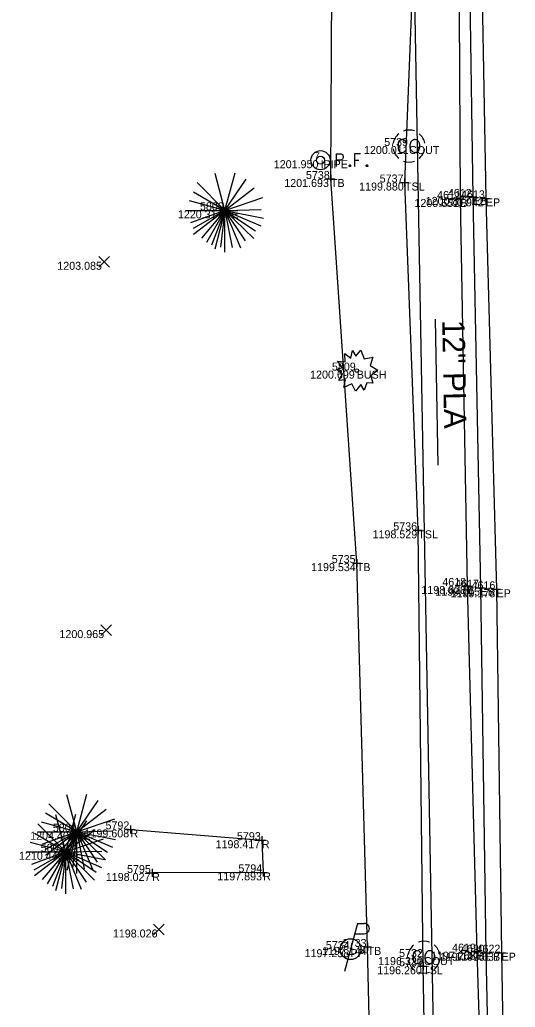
# Model space of a CAD drawing. Extents: x 2044996 to 2050343, y 455232 to 458054.
# Drawn here: x 2047573.6 to 2047635.5, y 456392.6 to 456516 of the extents above; entities that cross this region are included whole.
import ezdxf

# ---------------------------------------------------------------- set-up
doc = ezdxf.new("R2010")
doc.units = 0
for name, color, linetype in [('DR_X_Cells', 7, 'Continuous'), ('DR_X_Erosion_Control', 7, 'Continuous'), ('DR_X_Storm_Sewer', 7, 'Continuous'), ('DR_X_Text', 7, 'Continuous'), ('DT_X_Contour_Minor', 7, 'Continuous'), ('DT_X_Contour_Text', 7, 'Continuous'), ('DT_X_Spot_Elev', 7, 'Continuous'), ('DT_X_Triangles', 7, 'Continuous'), ('DT_X_Void', 7, 'Continuous'), ('PV_X_EOP', 7, 'Continuous'), ('PV_X_Shoulder_Aggregate', 7, 'Continuous'), ('SV_X_Break_Lines', 7, 'Continuous'), ('SV_X_Toe_of_Slope', 7, 'Continuous'), ('SV_X_Top_of_Bank', 7, 'Continuous'), ('UT_X_Electric_Cells', 7, 'Continuous'), ('VG_X_Cells', 7, 'Continuous'), ('XS_X_Ground_Line', 7, 'Continuous')]:
    doc.layers.add(name, color=color, linetype=linetype)

msp = doc.modelspace()

# ---------------------------------------------------------------- linework, layer by layer
at = {"layer": 'DR_X_Cells'}
for p, q in [((2047622.18, 456500.21), (2047622.18, 456500.21)), ((2047624.05, 456398.84), (2047624.05, 456398.84))]:
    msp.add_line(p, q, dxfattribs=at)
for points in [[(2047621.76, 456500.7), (2047621.7, 456500.84), (2047621.64, 456500.91), (2047621.58, 456500.96), (2047621.52, 456500.99), (2047621.39, 456501.01), (2047621.25, 456501.01), (2047621.07, 456500.96), (2047620.97, 456500.89), (2047620.92, 456500.82), (2047620.87, 456500.74), (2047620.83, 456500.6), (2047620.82, 456500.34), (2047620.82, 456500.16), (2047620.82, 456500.03), (2047620.83, 456499.92), (2047620.87, 456499.71), (2047620.88, 456499.68), (2047620.93, 456499.59), (2047620.98, 456499.53), (2047621.07, 456499.46), (2047621.15, 456499.44), (2047621.25, 456499.41), (2047621.36, 456499.41), (2047621.47, 456499.43), (2047621.51, 456499.44), (2047621.56, 456499.46), (2047621.61, 456499.51), (2047621.68, 456499.58), (2047621.73, 456499.65), (2047621.76, 456499.71)], [(2047622.78, 456501), (2047622.75, 456500.99), (2047622.71, 456500.97), (2047622.65, 456500.94), (2047622.61, 456500.91), (2047622.55, 456500.86), (2047622.49, 456500.81), (2047622.47, 456500.79), (2047622.43, 456500.74), (2047622.37, 456500.61), (2047622.32, 456500.48), (2047622.29, 456500.37), (2047622.28, 456500.21), (2047622.29, 456500.03), (2047622.33, 456499.9), (2047622.37, 456499.8), (2047622.39, 456499.75), (2047622.43, 456499.69), (2047622.48, 456499.63), (2047622.52, 456499.59), (2047622.56, 456499.55), (2047622.61, 456499.51), (2047622.67, 456499.48), (2047622.78, 456499.43), (2047622.85, 456499.41), (2047622.97, 456499.41), (2047623.02, 456499.43), (2047623.07, 456499.44), (2047623.14, 456499.46), (2047623.2, 456499.5), (2047623.24, 456499.53), (2047623.28, 456499.55), (2047623.31, 456499.59), (2047623.35, 456499.64), (2047623.38, 456499.68), (2047623.4, 456499.71), (2047623.43, 456499.75), (2047623.46, 456499.83), (2047623.5, 456499.92), (2047623.53, 456500.02), (2047623.54, 456500.11), (2047623.54, 456500.12), (2047623.54, 456500.21), (2047623.54, 456500.28), (2047623.53, 456500.38), (2047623.5, 456500.48), (2047623.48, 456500.56), (2047623.44, 456500.65), (2047623.4, 456500.72), (2047623.34, 456500.8), (2047623.29, 456500.85), (2047623.24, 456500.9), (2047623.19, 456500.94), (2047623.11, 456500.97), (2047623.04, 456501), (2047622.96, 456501.01), (2047622.87, 456501.01), (2047622.78, 456501)], [(2047623.64, 456399.32), (2047623.58, 456399.46), (2047623.51, 456399.54), (2047623.45, 456399.59), (2047623.4, 456399.61), (2047623.26, 456399.64), (2047623.12, 456399.64), (2047622.95, 456399.59), (2047622.85, 456399.51), (2047622.8, 456399.45), (2047622.75, 456399.36), (2047622.71, 456399.22), (2047622.7, 456398.97), (2047622.7, 456398.78), (2047622.7, 456398.65), (2047622.71, 456398.54), (2047622.75, 456398.34), (2047622.76, 456398.3), (2047622.81, 456398.21), (2047622.86, 456398.15), (2047622.95, 456398.09), (2047623.02, 456398.06), (2047623.12, 456398.04), (2047623.24, 456398.04), (2047623.35, 456398.05), (2047623.39, 456398.06), (2047623.44, 456398.09), (2047623.49, 456398.14), (2047623.55, 456398.2), (2047623.6, 456398.28), (2047623.64, 456398.34)], [(2047624.66, 456399.62), (2047624.62, 456399.61), (2047624.59, 456399.6), (2047624.52, 456399.56), (2047624.48, 456399.54), (2047624.42, 456399.49), (2047624.37, 456399.43), (2047624.35, 456399.41), (2047624.31, 456399.36), (2047624.25, 456399.23), (2047624.19, 456399.11), (2047624.17, 456398.99), (2047624.16, 456398.83), (2047624.17, 456398.65), (2047624.21, 456398.53), (2047624.25, 456398.43), (2047624.27, 456398.38), (2047624.31, 456398.31), (2047624.36, 456398.25), (2047624.4, 456398.21), (2047624.43, 456398.17), (2047624.48, 456398.14), (2047624.55, 456398.1), (2047624.66, 456398.05), (2047624.72, 456398.04), (2047624.85, 456398.04), (2047624.9, 456398.05), (2047624.95, 456398.06), (2047625.01, 456398.09), (2047625.08, 456398.12), (2047625.11, 456398.15), (2047625.15, 456398.17), (2047625.19, 456398.21), (2047625.23, 456398.26), (2047625.25, 456398.3), (2047625.28, 456398.34), (2047625.3, 456398.38), (2047625.34, 456398.45), (2047625.38, 456398.54), (2047625.4, 456398.64), (2047625.42, 456398.73), (2047625.42, 456398.74), (2047625.42, 456398.83), (2047625.42, 456398.91), (2047625.4, 456399.01), (2047625.38, 456399.11), (2047625.35, 456399.18), (2047625.32, 456399.27), (2047625.28, 456399.35), (2047625.21, 456399.42), (2047625.16, 456399.47), (2047625.11, 456399.52), (2047625.06, 456399.56), (2047624.99, 456399.6), (2047624.91, 456399.62), (2047624.84, 456399.64), (2047624.75, 456399.64), (2047624.66, 456399.62)]]:
    msp.add_lwpolyline(points, dxfattribs=at)
for centre, start, end in [((2047622.18, 456500.21), 70.0577, 110.1061), ((2047622.18, 456500.21), 130.0806, 170.0721), ((2047622.18, 456500.21), 10.0169, 50.0392), ((2047622.18, 456500.21), 190.0169, 230.0392), ((2047622.18, 456500.21), 310.0114, 350.0264), ((2047622.18, 456500.21), 250.0577, 290.0473), ((2047624.05, 456398.83), 70.0577, 110.1061), ((2047624.05, 456398.83), 130.0806, 170.0721), ((2047624.05, 456398.83), 10.0169, 50.0392), ((2047624.05, 456398.83), 190.0169, 230.0392), ((2047624.05, 456398.83), 310.0114, 350.0264), ((2047624.05, 456398.83), 250.0577, 290.0473)]:
    msp.add_arc(centre, 2, start, end, dxfattribs=at)
at = {"layer": 'DR_X_Erosion_Control'}
msp.add_lwpolyline([(2047587.38, 456414.8), (2047603.8, 456413.45), (2047603.96, 456409.43), (2047590.09, 456409.35)], dxfattribs=at)
at = {"layer": 'DR_X_Storm_Sewer'}
msp.add_line((2047618.84, 456740.61), (2047628.62, 456202.21), dxfattribs=at)
at = {"layer": 'DR_X_Text'}
msp.add_line((2047625.83, 456460.34), (2047625.5, 456478.56), dxfattribs=at)
at = {"layer": 'DT_X_Spot_Elev'}
for p, q in [((2047583.43, 456485.07), (2047584.77, 456486.41)), ((2047583.43, 456486.41), (2047584.77, 456485.07)), ((2047583.7, 456439.04), (2047585.04, 456440.38)), ((2047583.7, 456440.38), (2047585.04, 456439.04)), ((2047590.26, 456401.63), (2047591.59, 456402.96)), ((2047590.26, 456402.96), (2047591.59, 456401.63))]:
    msp.add_line(p, q, dxfattribs=at)
at = {"layer": 'DT_X_Void'}
for p, q in [((2047611.93, 456496.09), (2047612.93, 456496.09)), ((2047612.43, 456496.59), (2047612.43, 456495.59)), ((2047612.43, 456496.09), (2047612.43, 456496.09)), ((2047621.68, 456496.15), (2047621.68, 456495.15)), ((2047621.18, 456495.65), (2047622.18, 456495.65)), ((2047621.68, 456495.65), (2047621.68, 456495.65)), ((2047628.08, 456493.59), (2047629.08, 456493.59)), ((2047628.58, 456494.09), (2047628.58, 456493.09)), ((2047628.58, 456493.59), (2047628.58, 456493.59)), ((2047629.65, 456493.85), (2047630.65, 456493.85)), ((2047630.15, 456494.35), (2047630.15, 456493.35)), ((2047630.15, 456493.85), (2047630.15, 456493.85)), ((2047631.28, 456493.67), (2047632.28, 456493.67)), ((2047631.78, 456494.17), (2047631.78, 456493.17)), ((2047631.78, 456493.67), (2047631.78, 456493.67)), ((2047623.34, 456452.68), (2047623.34, 456451.68)), ((2047622.84, 456452.18), (2047623.84, 456452.18)), ((2047623.34, 456452.18), (2047623.34, 456452.18)), ((2047615.16, 456448.08), (2047616.16, 456448.08)), ((2047615.66, 456448.58), (2047615.66, 456447.58)), ((2047615.66, 456448.08), (2047615.66, 456448.08)), ((2047628.96, 456445.22), (2047629.96, 456445.22)), ((2047629.46, 456445.72), (2047629.46, 456444.72)), ((2047629.46, 456445.22), (2047629.46, 456445.22)), ((2047631.11, 456445.51), (2047631.11, 456444.51)), ((2047633.11, 456445.31), (2047633.11, 456444.31)), ((2047630.61, 456445.01), (2047631.61, 456445.01)), ((2047631.11, 456445.01), (2047631.11, 456445.01)), ((2047632.61, 456444.81), (2047633.61, 456444.81)), ((2047633.11, 456444.81), (2047633.11, 456444.81)), ((2047586.88, 456414.8), (2047587.88, 456414.8)), ((2047587.38, 456415.3), (2047587.38, 456414.3)), ((2047587.38, 456414.8), (2047587.38, 456414.8)), ((2047603.3, 456413.45), (2047604.3, 456413.45)), ((2047603.8, 456413.95), (2047603.8, 456412.95)), ((2047603.8, 456413.45), (2047603.8, 456413.45)), ((2047589.59, 456409.35), (2047590.59, 456409.35)), ((2047590.09, 456409.85), (2047590.09, 456408.85)), ((2047590.09, 456409.35), (2047590.09, 456409.35)), ((2047603.46, 456409.43), (2047604.46, 456409.43)), ((2047603.96, 456409.93), (2047603.96, 456408.93)), ((2047603.96, 456409.43), (2047603.96, 456409.43)), ((2047616.51, 456400.11), (2047617.51, 456400.11)), ((2047617.01, 456400.61), (2047617.01, 456399.61)), ((2047617.01, 456400.11), (2047617.01, 456400.11)), ((2047630.16, 456399.52), (2047631.16, 456399.52)), ((2047630.66, 456400.02), (2047630.66, 456399.02)), ((2047630.66, 456399.52), (2047630.66, 456399.52)), ((2047631.78, 456399.88), (2047631.78, 456398.88)), ((2047633.74, 456399.89), (2047633.74, 456398.89)), ((2047623.95, 456398.19), (2047623.95, 456397.19)), ((2047631.28, 456399.38), (2047632.28, 456399.38)), ((2047631.78, 456399.38), (2047631.78, 456399.38)), ((2047633.24, 456399.39), (2047634.24, 456399.39)), ((2047633.74, 456399.39), (2047633.74, 456399.39)), ((2047623.45, 456397.69), (2047624.45, 456397.69)), ((2047623.95, 456397.69), (2047623.95, 456397.69))]:
    msp.add_line(p, q, dxfattribs=at)
at = {"layer": 'PV_X_EOP'}
for p, q in [((2047630.94, 456539.92), (2047631.78, 456493.67)), ((2047631.78, 456493.67), (2047633.11, 456444.81)), ((2047633.11, 456444.81), (2047633.74, 456399.39)), ((2047633.74, 456399.39), (2047634.49, 456356.94))]:
    msp.add_line(p, q, dxfattribs=at)
at = {"layer": 'PV_X_Shoulder_Aggregate'}
for p, q in [((2047629.49, 456539.93), (2047630.15, 456493.85)), ((2047630.15, 456493.85), (2047631.11, 456445.01)), ((2047631.11, 456445.01), (2047631.78, 456399.38)), ((2047631.78, 456399.38), (2047632.62, 456356.87))]:
    msp.add_line(p, q, dxfattribs=at)
at = {"layer": 'SV_X_Break_Lines'}
msp.add_lwpolyline([(2047625.21, 456638.95), (2047627.11, 456588.81), (2047628.32, 456540.51), (2047628.58, 456493.59), (2047629.46, 456445.22), (2047630.66, 456399.52), (2047631.97, 456357.07), (2047632.12, 456312.85), (2047632.56, 456284.1)], dxfattribs=at)
at = {"layer": 'SV_X_Toe_of_Slope'}
msp.add_lwpolyline([(2047627.42, 456261.1), (2047625.53, 456304.38), (2047624.71, 456355.98), (2047623.95, 456397.69), (2047623.34, 456452.18), (2047621.68, 456495.65), (2047623.55, 456542.59), (2047620.93, 456580.31), (2047618.38, 456635.97)], dxfattribs=at)
at = {"layer": 'SV_X_Top_of_Bank'}
msp.add_lwpolyline([(2047619.16, 456260.18), (2047618.27, 456307.13), (2047618.14, 456352.85), (2047617.01, 456400.11), (2047615.66, 456448.08), (2047612.43, 456496.09), (2047612.66, 456543.64), (2047611.43, 456577.89), (2047611.46, 456637.59)], dxfattribs=at)
at = {"layer": 'UT_X_Electric_Cells'}
for p, q in [((2047615.73, 456403.03), (2047614.13, 456397.03)), ((2047615.73, 456403.03), (2047616.58, 456403.03)), ((2047615.39, 456401.76), (2047616.58, 456401.76))]:
    msp.add_line(p, q, dxfattribs=at)
msp.add_circle((2047614.88, 456399.83), 1.3, dxfattribs=at)
msp.add_arc((2047616.6, 456402.4), 0.638, 268.8767, 91.1233, dxfattribs=at)
at = {"layer": 'VG_X_Cells'}
for p, q in [((2047599.19, 456492.17), (2047597.96, 456496.78)), ((2047599.19, 456492.17), (2047600.45, 456496.87)), ((2047599.19, 456492.17), (2047601.85, 456496.05)), ((2047599.19, 456492.17), (2047595.28, 456494.46)), ((2047599.19, 456492.17), (2047595.7, 456495.65)), ((2047599.19, 456492.17), (2047602.85, 456494.97)), ((2047599.19, 456492.17), (2047594.78, 456493.35)), ((2047599.19, 456492.17), (2047603.93, 456493.77)), ((2047594.26, 456492.17), (2047599.19, 456492.17)), ((2047599.19, 456492.17), (2047594.9, 456490.61)), ((2047599.19, 456492.17), (2047595.21, 456489.89)), ((2047599.19, 456492.17), (2047595.28, 456489.17)), ((2047599.19, 456492.17), (2047596.25, 456488.7)), ((2047599.19, 456492.17), (2047596.87, 456488.15)), ((2047599.19, 456492.17), (2047597.53, 456487.83)), ((2047599.19, 456492.17), (2047597.93, 456487.31)), ((2047599.19, 456492.17), (2047598.65, 456487.58)), ((2047599.19, 456492.17), (2047603.7, 456492.26)), ((2047599.19, 456486.93), (2047599.19, 456492.17)), ((2047599.19, 456492.17), (2047600.11, 456487.53)), ((2047599.19, 456492.17), (2047601.12, 456487.5)), ((2047599.19, 456492.17), (2047601.73, 456488.37)), ((2047599.19, 456492.17), (2047602.78, 456488.65)), ((2047599.19, 456492.17), (2047603.01, 456489.61)), ((2047599.19, 456492.17), (2047603.66, 456490.23)), ((2047599.19, 456492.17), (2047604.02, 456491.21)), ((2047580.69, 456414.51), (2047581.95, 456419.21)), ((2047580.69, 456414.51), (2047577.2, 456418)), ((2047580.69, 456414.51), (2047579.46, 456419.13)), ((2047580.69, 456414.51), (2047583.35, 456418.4)), ((2047580.69, 456414.51), (2047576.79, 456416.81)), ((2047579.3, 456412), (2047580.56, 456416.69)), ((2047580.69, 456414.51), (2047584.35, 456417.32)), ((2047579.3, 456412), (2047575.81, 456415.48)), ((2047580.69, 456414.51), (2047576.28, 456415.7)), ((2047579.3, 456412), (2047578.06, 456416.61)), ((2047579.3, 456412), (2047581.95, 456415.88)), ((2047580.69, 456414.51), (2047585.43, 456416.12)), ((2047579.3, 456412), (2047575.39, 456414.29)), ((2047575.76, 456414.51), (2047580.69, 456414.51)), ((2047580.69, 456414.51), (2047576.4, 456412.95)), ((2047580.69, 456414.51), (2047576.71, 456412.23)), ((2047580.69, 456414.51), (2047576.79, 456411.52)), ((2047580.69, 456414.51), (2047577.75, 456411.05)), ((2047580.69, 456414.51), (2047578.37, 456410.5)), ((2047580.69, 456414.51), (2047579.03, 456410.17)), ((2047579.3, 456412), (2047582.96, 456414.8)), ((2047580.69, 456414.51), (2047579.43, 456409.66)), ((2047580.69, 456414.51), (2047580.15, 456409.92)), ((2047580.69, 456414.51), (2047585.2, 456414.6)), ((2047580.69, 456409.27), (2047580.69, 456414.51)), ((2047580.69, 456414.51), (2047581.61, 456409.88)), ((2047580.69, 456414.51), (2047582.63, 456409.84)), ((2047580.69, 456414.51), (2047583.23, 456410.72)), ((2047580.69, 456414.51), (2047584.28, 456410.99)), ((2047580.69, 456414.51), (2047584.51, 456411.96)), ((2047580.69, 456414.51), (2047585.16, 456412.57)), ((2047580.69, 456414.51), (2047585.52, 456413.55)), ((2047579.3, 456412), (2047574.89, 456413.18)), ((2047579.3, 456412), (2047584.04, 456413.6)), ((2047574.36, 456412), (2047579.3, 456412)), ((2047579.3, 456412), (2047575.01, 456410.43)), ((2047579.3, 456412), (2047575.32, 456409.71)), ((2047579.3, 456412), (2047575.39, 456409)), ((2047579.3, 456412), (2047576.35, 456408.53)), ((2047579.3, 456412), (2047576.98, 456407.98)), ((2047579.3, 456412), (2047577.63, 456407.66)), ((2047579.3, 456412), (2047578.04, 456407.14)), ((2047579.3, 456412), (2047578.76, 456407.4)), ((2047579.3, 456412), (2047583.81, 456412.09)), ((2047579.3, 456406.76), (2047579.3, 456412)), ((2047579.3, 456412), (2047580.22, 456407.36)), ((2047579.3, 456412), (2047581.23, 456407.33)), ((2047579.3, 456412), (2047581.84, 456408.2)), ((2047579.3, 456412), (2047582.89, 456408.47)), ((2047579.3, 456412), (2047583.12, 456409.44)), ((2047579.3, 456412), (2047583.76, 456410.05)), ((2047579.3, 456412), (2047584.13, 456411.04))]:
    msp.add_line(p, q, dxfattribs=at)
msp.add_lwpolyline([(2047615.56, 456473.95), (2047616.17, 456474.69), (2047616.58, 456473.63), (2047617.67, 456473.81), (2047617.34, 456472.8), (2047618.28, 456472.21), (2047617.42, 456471.47), (2047617.67, 456470.56), (2047616.92, 456470.63), (2047616.6, 456469.71), (2047616.17, 456470.4), (2047615.49, 456469.59), (2047615.06, 456470.47), (2047614.04, 456470.04), (2047614.23, 456470.99), (2047613.42, 456470.9), (2047613.89, 456471.69), (2047613.13, 456472.26), (2047613.86, 456472.52), (2047613.26, 456473.33), (2047614.19, 456473.22), (2047614.16, 456474.26), (2047614.91, 456473.69), (2047615.12, 456474.67), (2047615.56, 456473.95)], dxfattribs=at)
msp.add_circle((2047615.65, 456472.14), 0.23, dxfattribs=at)
at = {"layer": 'XS_X_Ground_Line'}
for points in [[(2047613.12, 456497.64), (2047613.12, 456499.24), (2047613.65, 456499.24), (2047613.71, 456499.23), (2047613.79, 456499.2), (2047613.82, 456499.18), (2047613.85, 456499.15), (2047613.9, 456499.09), (2047613.93, 456499.02), (2047613.95, 456498.92), (2047613.95, 456498.77), (2047613.94, 456498.72), (2047613.92, 456498.65), (2047613.87, 456498.56), (2047613.83, 456498.52), (2047613.8, 456498.5), (2047613.74, 456498.47), (2047613.65, 456498.46), (2047613.12, 456498.46)], [(2047616.13, 456499.24), (2047615.37, 456499.24), (2047615.37, 456497.64)], [(2047615.37, 456498.46), (2047615.91, 456498.46)], [(2047614.77, 456497.85), (2047614.82, 456497.85), (2047614.86, 456497.83), (2047614.89, 456497.78), (2047614.89, 456497.71), (2047614.86, 456497.66), (2047614.82, 456497.64), (2047614.77, 456497.64), (2047614.73, 456497.66), (2047614.7, 456497.71), (2047614.7, 456497.78), (2047614.73, 456497.83), (2047614.77, 456497.85)], [(2047616.92, 456497.85), (2047616.97, 456497.85), (2047617, 456497.83), (2047617.04, 456497.78), (2047617.04, 456497.71), (2047617, 456497.66), (2047616.97, 456497.64), (2047616.92, 456497.64), (2047616.88, 456497.66), (2047616.85, 456497.71), (2047616.85, 456497.78), (2047616.88, 456497.83), (2047616.92, 456497.85)]]:
    msp.add_lwpolyline(points, dxfattribs=at)
for radius in [1.2, 0.495]:
    msp.add_circle((2047611.13, 456498.44), radius, dxfattribs=at)

# ---------------------------------------------------------------- texts
at = {"layer": 'DR_X_Text'}
msp.add_text('12" PLA', height=2.8, rotation=271.0413, dxfattribs=at).set_placement((2047626.33, 456478.47))
at = {"layer": 'DT_X_Contour_Minor'}
for s, p in [('1200.011', (2047616.56, 456499.21)), ('1201.950', (2047605.29, 456497.44)), ('1201.693', (2047606.6, 456495.09)), ('1199.880', (2047615.95, 456494.65)), ('1200.651', (2047622.86, 456492.59)), ('1200.877', (2047624.27, 456492.85)), ('1200.942', (2047625.95, 456492.67)), ('1220.317', (2047593.31, 456491.17)), ('1203.085', (2047578.25, 456484.74)), ('1200.699', (2047609.83, 456471.14)), ('1198.529', (2047617.63, 456451.18)), ('1199.534', (2047609.95, 456447.08)), ('1198.828', (2047623.72, 456444.22)), ('1199.115', (2047625.47, 456444.01)), ('1199.178', (2047627.38, 456443.81)), ('1200.965', (2047578.52, 456438.71)), ('1204.402', (2047574.86, 456413.51)), ('1199.608', (2047581.65, 456413.8)), ('1198.417', (2047598.02, 456412.45)), ('1210.446', (2047573.46, 456411)), ('1198.027', (2047584.31, 456408.35)), ('1197.893', (2047598.24, 456408.43)), ('1198.026', (2047585.19, 456401.29)), ('1197.258', (2047609.14, 456398.83)), ('1197.144', (2047611.31, 456399.11)), ('1197.268', (2047624.93, 456398.52)), ('1197.637', (2047627.96, 456398.39)), ('1196.320', (2047618.32, 456397.84)), ('1197.496', (2047626.05, 456398.38)), ('1196.260', (2047618.21, 456396.69))]:
    msp.add_text(s, height=1, dxfattribs=at).set_placement(p)
at = {"layer": 'DT_X_Contour_Text'}
for s, p in [('COUT', (2047622.18, 456499.21)), ('IPIPE', (2047611.13, 456497.44)), ('TB', (2047612.43, 456495.09)), ('TSL', (2047621.68, 456494.65)), ('B', (2047628.58, 456492.59)), ('EB', (2047630.15, 456492.85)), ('EP', (2047631.78, 456492.67)), ('TE', (2047599.19, 456491.17)), ('BUSH', (2047615.65, 456471.14)), ('TSL', (2047623.34, 456451.18)), ('TB', (2047615.66, 456447.08)), ('B', (2047629.46, 456444.22)), ('EB', (2047631.11, 456444.01)), ('EP', (2047633.11, 456443.81)), ('TE', (2047580.69, 456413.51)), ('R', (2047587.38, 456413.8)), ('R', (2047603.8, 456412.45)), ('TE', (2047579.3, 456411)), ('R', (2047590.09, 456408.35)), ('R', (2047603.96, 456408.43)), ('PP', (2047614.88, 456398.83)), ('TB', (2047617.01, 456399.11)), ('B', (2047630.66, 456398.52)), ('COUT', (2047624.05, 456397.84)), ('EB', (2047631.78, 456398.38)), ('EP', (2047633.74, 456398.39)), ('TSL', (2047623.95, 456396.69))]:
    msp.add_text(s, height=1, dxfattribs=at).set_placement(p)
at = {"layer": 'DT_X_Triangles'}
for s, p in [('5739', (2047619.08, 456500.21)), ('7', (2047610.3, 456498.44)), ('5738', (2047609.31, 456496.09)), ('5737', (2047618.52, 456495.65)), ('4611', (2047625.68, 456493.59)), ('4612', (2047627.04, 456493.85)), ('4613', (2047628.68, 456493.67)), ('5800', (2047596.07, 456492.17)), ('5809', (2047612.55, 456472.14)), ('5736', (2047620.22, 456452.18)), ('5735', (2047612.53, 456448.08)), ('4618', (2047626.34, 456445.22)), ('4617', (2047627.95, 456445.01)), ('4616', (2047629.99, 456444.81)), ('5801', (2047577.69, 456414.51)), ('5792', (2047584.27, 456414.8)), ('5793', (2047600.69, 456413.45)), ('5802', (2047576.18, 456412)), ('5795', (2047586.96, 456409.35)), ('5794', (2047600.87, 456409.43)), ('5734', (2047611.79, 456399.83)), ('5733', (2047613.9, 456400.11)), ('5732', (2047620.94, 456398.84)), ('4619', (2047627.56, 456399.52)), ('4620', (2047628.66, 456399.38)), ('4622', (2047630.62, 456399.39)), ('5731', (2047620.95, 456397.69))]:
    msp.add_text(s, height=1, dxfattribs=at).set_placement(p)

doc.saveas('drawing.dxf')
